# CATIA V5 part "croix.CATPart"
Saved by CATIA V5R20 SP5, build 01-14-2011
Part number: croix
Bounding box of the stored display mesh (mm): x -4 to 4, y -22 to 22, z -30 to 30
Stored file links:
  E:\IAO_2010\iao\IAO_MMS_Groupe2\IAO_MMS_Groupe2\melguidj\Catia\croix.CATPart
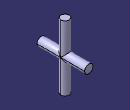
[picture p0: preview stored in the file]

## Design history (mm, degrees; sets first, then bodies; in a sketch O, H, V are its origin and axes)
Body1 (main body)
  Sketch1 on zx-plane, origin (0, 0, 0), H (-1, 0, 0), V (0, 0, 1)
    circle A1 centre (0, 0) radius 4
    radius A1 = 4
  Pad1: profile Sketch1, direction (0, 1, 0), length 22, mirrored extent
  Sketch2 on xy-plane, origin (0, 0, 0), H (1, 0, 0), V (0, 1, 0)
    circle A1 centre (0, 0) radius 4
    radius A1 = 4
  Pad2: profile Sketch2, direction (0, 0, 1), length 30, mirrored extent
